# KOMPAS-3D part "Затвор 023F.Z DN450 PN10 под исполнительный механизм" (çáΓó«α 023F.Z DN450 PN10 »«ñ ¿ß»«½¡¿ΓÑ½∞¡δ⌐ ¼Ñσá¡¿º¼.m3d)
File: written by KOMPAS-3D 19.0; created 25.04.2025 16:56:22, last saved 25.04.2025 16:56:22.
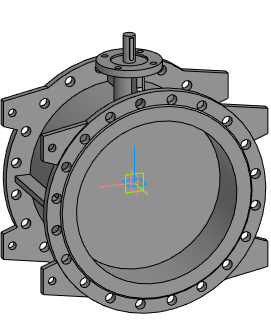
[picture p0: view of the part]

Document properties: Автор: Евгений; Полное имя файла: E:\Dendor Работа Сачек\3D для проекитирвщиков\1.7 Тип 023F.Z Затвор дисковый поворотный фланцевый с двумя эксцентриками\stp_Тип 023F.Z. Затвор под исполн. механизм\Затвор 023F.Z DN450 PN10 под исполнительный механизм.m3d

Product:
- Part/product: Затвор 023F.Z DN450 PN10 под исполнительный механизм

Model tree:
1. Операция без истории:1  (labels: Затвор 023F.Z DN450 PN10 под исполнительный механизм)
